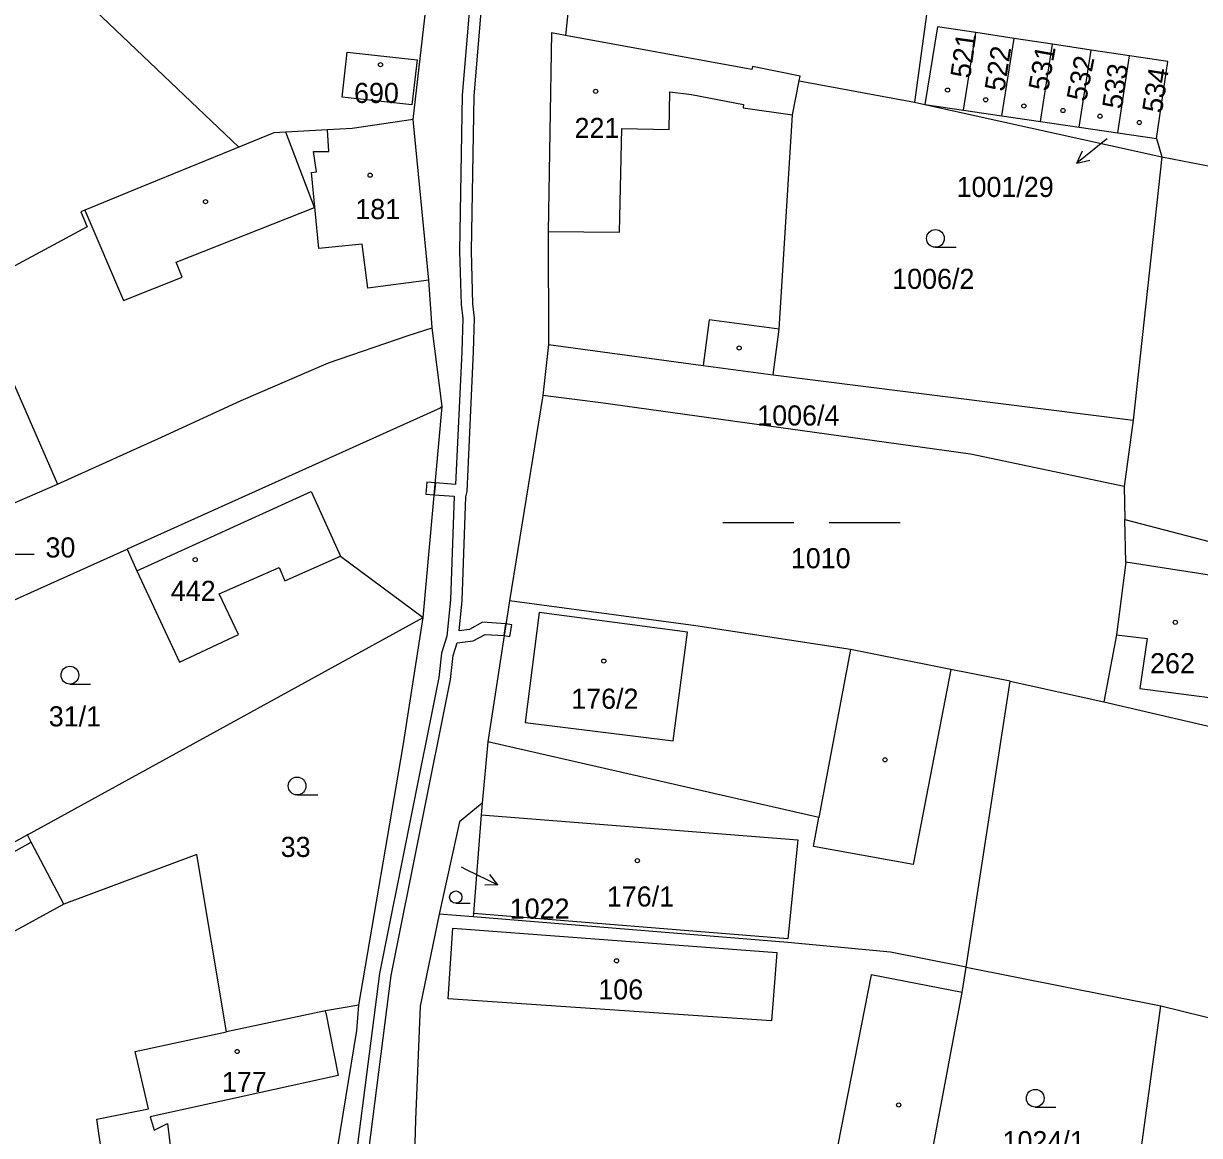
# Model space of a CAD drawing. Extents: x -776734 to -748832, y -1118122 to -976986.
# Drawn here: x -752895.7 to -752796.2, y -1115665 to -1115570.9 of the extents above; entities that cross this region are included whole.
import ezdxf

# ---------------------------------------------------------------- set-up
doc = ezdxf.new("R2010")
doc.units = 0
for name, color, linetype in [('KM_Hranice parcel', 7, 'Continuous'), ('KM_Parcelní čísla', 7, 'Continuous'), ('KM_Pop  PČ popisy', 7, 'Continuous'), ('KM_Vnitřní kresba', 7, 'Continuous'), ('KM_Věcná břemena k části', 7, 'Continuous'), ('KM_Značky budov', 7, 'Continuous'), ('KM_Značky kultur', 7, 'Continuous')]:
    doc.layers.add(name, color=color, linetype=linetype)

msp = doc.modelspace()

# ---------------------------------------------------------------- linework, layer by layer
at = {"layer": 'KM_Hranice parcel'}
for p, q in [((-752848.27, -1115557.37), (-752849.84, -1115571.95)), ((-752817.98, -1115560.51), (-752820.33, -1115577.6)), ((-752877.46, -1115581.39), (-752897.05, -1115562.76)), ((-752862.74, -1115579.05), (-752860.83, -1115562.74)), ((-752816.2, -1115578.27), (-752815.15, -1115571.71)), ((-752811.9, -1115572.2), (-752815.15, -1115571.71)), ((-752812.94, -1115578.75), (-752811.9, -1115572.2)), ((-752808.65, -1115572.69), (-752811.9, -1115572.2)), ((-752809.67, -1115579.22), (-752808.65, -1115572.69)), ((-752805.4, -1115573.18), (-752808.65, -1115572.69)), ((-752806.41, -1115579.7), (-752805.4, -1115573.18)), ((-752802.15, -1115573.67), (-752805.4, -1115573.18)), ((-752803.14, -1115580.18), (-752802.15, -1115573.67)), ((-752830.08, -1115575.78), (-752820.33, -1115577.6)), ((-752820.33, -1115577.6), (-752819.46, -1115577.79)), ((-752819.46, -1115577.79), (-752816.2, -1115578.27)), ((-752819.46, -1115577.79), (-752799.43, -1115582.21)), ((-752816.2, -1115578.27), (-752812.94, -1115578.75)), ((-752812.94, -1115578.75), (-752809.67, -1115579.22)), ((-752809.67, -1115579.22), (-752806.41, -1115579.7)), ((-752806.41, -1115579.7), (-752803.14, -1115580.18)), ((-752803.14, -1115580.18), (-752799.88, -1115580.66)), ((-752799.88, -1115580.66), (-752799.43, -1115582.21)), ((-752799.43, -1115582.21), (-752801.84, -1115604.48)), ((-752799.43, -1115582.21), (-752794.17, -1115583.22)), ((-752890.84, -1115586.86), (-752890.29, -1115588.13)), ((-752890.29, -1115588.13), (-752900.02, -1115593.37)), ((-752900.02, -1115593.37), (-752892.81, -1115609.9)), ((-752860.27, -1115603.32), (-752861.11, -1115596.67)), ((-752851.29, -1115598.07), (-752851.77, -1115602.39)), ((-752832.29, -1115600.65), (-752801.84, -1115604.48)), ((-752851.77, -1115602.39), (-752854.58, -1115619.76)), ((-752861.88, -1115621.17), (-752860.27, -1115603.32)), ((-752801.84, -1115604.48), (-752802.6, -1115610.08)), ((-752802.6, -1115610.08), (-752802.54, -1115612.87)), ((-752802.54, -1115612.87), (-752750.63, -1115626.49)), ((-752802.47, -1115616.49), (-752802.54, -1115612.87)), ((-752907.48, -1115624.64), (-752886.91, -1115615.38)), ((-752854.58, -1115619.76), (-752856.41, -1115631.69)), ((-752895.34, -1115639.55), (-752861.88, -1115621.17)), ((-752815.97, -1115650.74), (-752812.23, -1115626.56)), ((-752812.23, -1115626.56), (-752804.31, -1115628.3)), ((-752804.31, -1115628.3), (-752792.23, -1115631.1)), ((-752856.41, -1115631.69), (-752856.89, -1115636.87)), ((-752895.34, -1115639.55), (-752898.57, -1115641.32)), ((-752857.65, -1115646.48), (-752860.52, -1115646.26)), ((-752815.97, -1115650.74), (-752799.51, -1115654.01)), ((-752799.51, -1115654.01), (-752770.11, -1115661.14))]:
    msp.add_line(p, q, dxfattribs=at)
for points in [[(-752849.84, -1115571.95), (-752851.03, -1115571.73), (-752851.32, -1115588.53), (-752851.29, -1115598.07)], [(-752815.15, -1115571.71), (-752818.4, -1115571.22), (-752819.46, -1115577.79)], [(-752830.08, -1115575.78), (-752830, -1115575.39), (-752834.04, -1115574.57), (-752834.09, -1115574.82), (-752849.84, -1115571.95)], [(-752868.31, -1115573.36), (-752862.4, -1115574.02), (-752862.83, -1115577.82), (-752868.73, -1115577.16), (-752868.31, -1115573.36)], [(-752799.88, -1115580.66), (-752798.9, -1115574.16), (-752802.15, -1115573.67)], [(-752832.29, -1115600.65), (-752831.77, -1115596.79), (-752830.66, -1115578.65), (-752830.08, -1115575.78)], [(-752862.74, -1115579.05), (-752867.89, -1115579.83), (-752869.97, -1115579.94), (-752873.5, -1115580.13), (-752874.5, -1115580.18), (-752877.46, -1115581.39)], [(-752861.11, -1115596.67), (-752861.39, -1115592.64), (-752862.74, -1115579.05)], [(-752877.46, -1115581.39), (-752885.77, -1115584.79), (-752890.48, -1115586.71), (-752890.84, -1115586.86)], [(-752892.81, -1115609.9), (-752884, -1115605.92), (-752877.26, -1115602.81), (-752869.9, -1115599.64), (-752863.16, -1115597.31), (-752861.11, -1115596.67)], [(-752851.29, -1115598.07), (-752838.2, -1115599.85), (-752832.29, -1115600.65)], [(-752802.6, -1115610.08), (-752815.59, -1115607.34), (-752846.87, -1115603.02), (-752851.77, -1115602.39)], [(-752860.27, -1115603.32), (-752860.43, -1115603.45), (-752886.91, -1115615.38)], [(-752929.59, -1115623.81), (-752927.65, -1115624.96), (-752892.81, -1115609.9)], [(-752886.91, -1115615.38), (-752886.09, -1115617.22), (-752882.49, -1115624.95), (-752877.51, -1115622.6), (-752879.14, -1115619.16), (-752874.07, -1115616.94), (-752873.57, -1115618.07), (-752868.87, -1115615.98), (-752861.88, -1115621.17)], [(-752802.47, -1115616.49), (-752803.25, -1115622.62), (-752804.31, -1115628.3)], [(-752792.23, -1115631.1), (-752791.88, -1115628.39), (-752791.22, -1115623.28), (-752794.37, -1115622.88), (-752793.59, -1115617.88), (-752802.47, -1115616.49)], [(-752825.73, -1115623.87), (-752838.82, -1115621.86), (-752854.58, -1115619.76)], [(-752867.31, -1115653.95), (-752863.57, -1115632.02), (-752861.88, -1115621.17)], [(-752825.73, -1115623.87), (-752828.41, -1115638.07), (-752856.41, -1115631.69)], [(-752812.23, -1115626.56), (-752817.25, -1115625.57), (-752825.73, -1115623.87)], [(-752856.89, -1115636.87), (-752858.82, -1115638.43), (-752860.52, -1115646.26)], [(-752856.89, -1115636.87), (-752856.97, -1115637.86), (-752857.63, -1115646.19), (-752857.65, -1115646.48)], [(-752878.51, -1115656.2), (-752881.01, -1115641.21), (-752892.27, -1115645.4), (-752895.02, -1115640.16), (-752895.34, -1115639.55)], [(-752860.52, -1115646.26), (-752862.14, -1115654.02), (-752862.52, -1115663.65), (-752862.64, -1115667.59), (-752862.57, -1115669.36)], [(-752815.97, -1115650.74), (-752822.36, -1115649.47), (-752831.05, -1115648.64), (-752857.65, -1115646.48)], [(-752820.03, -1115672.75), (-752819.9, -1115672.08), (-752816.31, -1115652.88), (-752815.97, -1115650.74)], [(-752867.31, -1115653.95), (-752870.14, -1115654.41), (-752878.51, -1115656.2)], [(-752869.62, -1115669.74), (-752869.34, -1115667.47), (-752867.48, -1115656.08), (-752867.31, -1115653.95)], [(-752805.59, -1115675.01), (-752801.91, -1115671.5), (-752799.51, -1115654.01)], [(-752891.85, -1115678.05), (-752891.62, -1115677.49), (-752892.23, -1115677.18), (-752889.79, -1115671.33), (-752888.85, -1115669.55), (-752889.03, -1115666.71), (-752889.48, -1115663.57), (-752885.12, -1115662.7), (-752886.24, -1115657.85), (-752878.51, -1115656.2)]]:
    msp.add_lwpolyline(points, dxfattribs=at)
at = {"layer": 'KM_Pop  PČ popisy'}
for p, q in [((-752804.05, -1115580.68), (-752804.26, -1115580.85)), ((-752804.26, -1115580.85), (-752806.592, -1115582.739)), ((-752806.592, -1115582.739), (-752806.129, -1115581.719)), ((-752806.592, -1115582.739), (-752805.499, -1115582.497)), ((-752858.67, -1115642.25), (-752858.25, -1115642.46)), ((-752858.25, -1115642.46), (-752855.553, -1115643.776)), ((-752855.553, -1115643.776), (-752856.233, -1115642.886)), ((-752855.553, -1115643.776), (-752856.672, -1115643.787))]:
    msp.add_line(p, q, dxfattribs=at)
at = {"layer": 'KM_Vnitřní kresba'}
for p, q in [((-752841.08, -1115579.9), (-752841.02, -1115576.71)), ((-752841.02, -1115576.71), (-752839.19, -1115576.93)), ((-752839.19, -1115576.93), (-752834.78, -1115577.8)), ((-752834.78, -1115577.8), (-752834.81, -1115578.07)), ((-752834.81, -1115578.07), (-752830.66, -1115578.65)), ((-752871.07, -1115586.51), (-752873.5, -1115580.13)), ((-752869.87, -1115581.75), (-752869.97, -1115579.94)), ((-752845.28, -1115588.58), (-752845.09, -1115579.82)), ((-752845.09, -1115579.82), (-752841.08, -1115579.9)), ((-752871.15, -1115581.77), (-752869.87, -1115581.75)), ((-752870.91, -1115583.49), (-752871.15, -1115581.77)), ((-752871.33, -1115583.53), (-752870.91, -1115583.49)), ((-752870.7, -1115589.96), (-752871.33, -1115583.53)), ((-752890.48, -1115586.71), (-752887.23, -1115594.36)), ((-752882.77, -1115591.13), (-752871.07, -1115586.51)), ((-752851.32, -1115588.53), (-752845.28, -1115588.58)), ((-752867.03, -1115589.6), (-752870.7, -1115589.96)), ((-752866.56, -1115593.31), (-752867.03, -1115589.6)), ((-752882.27, -1115592.4), (-752882.77, -1115591.13)), ((-752887.23, -1115594.36), (-752882.27, -1115592.4)), ((-752861.39, -1115592.64), (-752866.56, -1115593.31)), ((-752837.7, -1115595.99), (-752838.2, -1115599.85)), ((-752831.77, -1115596.79), (-752837.7, -1115595.99)), ((-752886.09, -1115617.22), (-752871.36, -1115610.52)), ((-752871.36, -1115610.52), (-752868.87, -1115615.98)), ((-752852.08, -1115620.75), (-752853.25, -1115630.03)), ((-752839.52, -1115622.39), (-752852.08, -1115620.75)), ((-752840.73, -1115631.58), (-752839.52, -1115622.39)), ((-752817.25, -1115625.57), (-752820.45, -1115642.06)), ((-752853.25, -1115630.03), (-752840.73, -1115631.58)), ((-752856.97, -1115637.86), (-752830.2, -1115639.97)), ((-752828.87, -1115640.52), (-752828.41, -1115638.07)), ((-752909.56, -1115648.16), (-752895.02, -1115640.16)), ((-752830.2, -1115639.97), (-752831.03, -1115648.34)), ((-752820.45, -1115642.06), (-752828.87, -1115640.52)), ((-752892.27, -1115645.4), (-752906.75, -1115653.3)), ((-752831.03, -1115648.34), (-752857.63, -1115646.19)), ((-752859.76, -1115653.41), (-752859.36, -1115647.42)), ((-752859.36, -1115647.42), (-752831.97, -1115649.5)), ((-752831.97, -1115649.5), (-752832.42, -1115655.26)), ((-752824.01, -1115651.39), (-752827.78, -1115670.61)), ((-752816.31, -1115652.88), (-752824.01, -1115651.39)), ((-752832.42, -1115655.26), (-752859.76, -1115653.41)), ((-752870.1, -1115654.6), (-752870.14, -1115654.41)), ((-752870.1, -1115654.6), (-752869.08, -1115659.88)), ((-752869.08, -1115659.88), (-752884.97, -1115663.39)), ((-752884.97, -1115663.39), (-752884.62, -1115664.52)), ((-752884.62, -1115664.52), (-752883.5, -1115663.96)), ((-752883.5, -1115663.96), (-752882.47, -1115672.4))]:
    msp.add_line(p, q, dxfattribs=at)
msp.add_lwpolyline([(-752803.25, -1115622.62), (-752800.65, -1115622.95), (-752801.28, -1115627.17), (-752791.88, -1115628.39)], dxfattribs=at)
at = {"layer": 'KM_Věcná břemena k části'}
for points in [[(-752857.11, -1115559.62), (-752858.57, -1115577.01), (-752858.8, -1115590.2), (-752858.67, -1115594.7), (-752858.54, -1115595.88), (-752858.62, -1115598.71), (-752859.14, -1115609.91), (-752860.85, -1115609.78), (-752860.94, -1115610.78), (-752859.26, -1115610.91), (-752859.57, -1115619.68), (-752859.88, -1115622.74), (-752860.32, -1115624.17)], [(-752866.48, -1115666.22), (-752864.58, -1115651.42), (-752859.58, -1115626.41), (-752859.34, -1115624.38), (-752859.01, -1115623.31), (-752857.66, -1115623.15), (-752856.63, -1115622.59), (-752855.03, -1115622.69), (-752854.88, -1115621.7), (-752856.85, -1115621.57), (-752857.97, -1115622.18), (-752858.83, -1115622.28), (-752858.57, -1115619.73), (-752858.26, -1115610.96), (-752858.16, -1115610.52), (-752857.62, -1115598.67), (-752857.54, -1115595.84), (-752857.67, -1115594.64), (-752857.8, -1115590.19), (-752857.57, -1115577.05), (-752856.16, -1115560.15)], [(-752860.32, -1115624.17), (-752860.57, -1115626.25), (-752865.57, -1115651.27), (-752867.54, -1115666.59)]]:
    msp.add_lwpolyline(points, dxfattribs=at)
for points in [[(-752860.94, -1115610.78), (-752860.85, -1115609.78), (-752861.57, -1115609.73), (-752861.65, -1115610.73)], [(-752854.54, -1115622.77), (-752854.38, -1115621.78), (-752854.88, -1115621.7), (-752855.03, -1115622.69)]]:
    msp.add_lwpolyline(points, close=True, dxfattribs=at)
at = {"layer": 'KM_Značky budov'}
for centre in [(-752865.4868, -1115574.4192), (-752847.2968, -1115576.6792), (-752817.5368, -1115576.5692), (-752814.3168, -1115577.3892), (-752811.0868, -1115577.9192), (-752807.7768, -1115578.2992), (-752804.6468, -1115578.7792), (-752801.3268, -1115579.3092), (-752866.3668, -1115583.7692), (-752880.2868, -1115586.0092), (-752835.1568, -1115598.3792), (-752881.1568, -1115616.2692), (-752798.2768, -1115621.5692), (-752846.6068, -1115624.8492), (-752822.8268, -1115633.1992), (-752843.7668, -1115641.7292), (-752845.5268, -1115650.1892), (-752877.6068, -1115657.8592), (-752821.6668, -1115662.3792)]:
    msp.add_circle(centre, 0.175, dxfattribs=at)
at = {"layer": 'KM_Značky kultur'}
for p, q in [((-752818.563, -1115589.86), (-752816.813, -1115589.86)), ((-752836.549, -1115613.13), (-752830.549, -1115613.13)), ((-752827.549, -1115613.13), (-752821.549, -1115613.13)), ((-752896.523, -1115615.8), (-752894.773, -1115615.8)), ((-752891.753, -1115626.79), (-752890.003, -1115626.79)), ((-752872.543, -1115636.16), (-752870.793, -1115636.16)), ((-752859.125, -1115645.33), (-752857.9, -1115645.33)), ((-752810.123, -1115662.56), (-752808.373, -1115662.56))]:
    msp.add_line(p, q, dxfattribs=at)
for centre, radius in [((-752818.5629, -1115589.1098), 0.75), ((-752891.7529, -1115626.0398), 0.75), ((-752872.5429, -1115635.4098), 0.75), ((-752859.125, -1115644.8049), 0.525), ((-752810.1229, -1115661.8098), 0.75)]:
    msp.add_circle(centre, radius, dxfattribs=at)

# ---------------------------------------------------------------- texts
at = {"layer": 'KM_Parcelní čísla'}
for s, rotation, p in [('521', 82, (-752815.628, -1115575.628)), ('522', 81, (-752812.74, -1115576.752)), ('531', 80, (-752809.042, -1115576.717)), ('532', 79, (-752805.825, -1115577.592)), ('533', 82, (-752802.788, -1115578.228)), ('534', 81, (-752799.42, -1115578.572))]:
    msp.add_text(s, height=1.7, rotation=rotation, dxfattribs=at).set_placement(p)
for s, p in [('690', (-752867.725, -1115577.66)), ('221', (-752849.08, -1115580.62)), ('1001/29', (-752816.773, -1115585.608)), ('181', (-752867.62, -1115587.48)), ('1006/2', (-752822.22, -1115593.38)), ('1006/4', (-752833.63, -1115604.93)), ('30', (-752893.82, -1115616.09)), ('1010', (-752830.79, -1115617)), ('442', (-752883.22, -1115619.76)), ('262', (-752800.41, -1115625.88)), ('176/2', (-752849.36, -1115628.88)), ('31/1', (-752893.54, -1115630.37)), ('33', (-752873.93, -1115641.41)), ('176/1', (-752846.35, -1115645.6)), ('1022', (-752854.56, -1115646.628)), ('106', (-752847.07, -1115653.46)), ('177', (-752878.9, -1115661.28)), ('1024/1', (-752812.89, -1115666.29))]:
    msp.add_text(s, height=1.7, dxfattribs=at).set_placement(p)

doc.saveas('drawing.dxf')
